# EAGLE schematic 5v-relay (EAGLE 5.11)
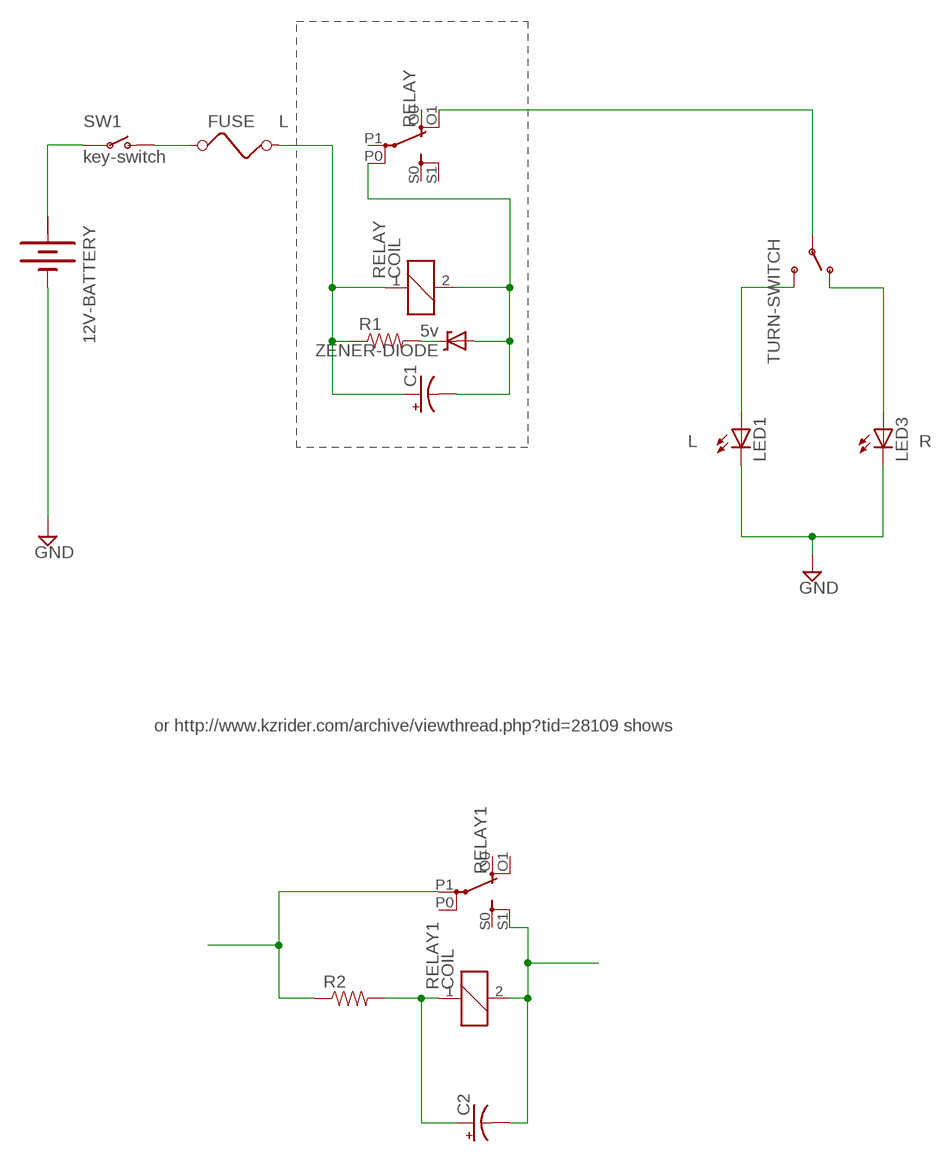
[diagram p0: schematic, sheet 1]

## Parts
12V-BATTERY  BATTERY  [BATTERY]
C1  CPOL-USA  [PANASONIC_A]
C2  CPOL-USA  [PANASONIC_A]
FUSE  FUSE  [FUSE]
LED1  LEDSQR2X5  [LED2X5]
LED3  LEDSQR2X5  [LED2X5]
R1  RESISTOR0402  [C0402]
R2  RESISTOR0402  [C0402]
RELAY  COIL  G2RE  [G2RE]
RELAY1  COIL  G2RE  [G2RE]
SW1  key-switch  SWITCH-SPST-2RA  [R_SW_TH]
TURN-SWITCH  SWITCH-SPSTPTH  [SWITCH-SPDT]
ZENER-DIODE  5v  DIODE-ZENERPTH  [DIODE-ZENER]

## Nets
GND: 12V-BATTERY.- LED1.K(C) LED3.K(C)
N$1: C1.+ FUSE.2 R1.1 RELAY.1
N$2: 12V-BATTERY.+ SW1.P$4(P)
N$3: C1.- RELAY.2 RELAY.P0(2:P) ZENER-DIODE.P$2(A)
N$4: LED3.A TURN-SWITCH.1(O)
N$5: LED1.A TURN-SWITCH.3(S)
N$6: RELAY.O1(2:O) TURN-SWITCH.2(P)
N$7: FUSE.1 SW1.P$3(O)
N$8: R1.2 ZENER-DIODE.P$1(C)
N$9: C2.- RELAY1.2 RELAY1.S1(2:S)
N$10: C2.+ R2.2 RELAY1.1
N$11: R2.1 RELAY1.P1(2:P)
Unconnected: RELAY1.O0(2:O) RELAY1.O1(2:O) RELAY1.P0(2:P) RELAY1.S0(2:S) RELAY.O0(2:O) RELAY.P1(2:P) RELAY.S0(2:S) RELAY.S1(2:S)

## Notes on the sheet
- L
- L | R
- or http://www.kzrider.com/archive/viewthread.php?tid=28109 shows

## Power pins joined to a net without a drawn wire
+: 12V-BATTERY.+@1(+)

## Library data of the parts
12V-BATTERY = special:BATTERY: BATTERY
C1 C2 = rcl:CPOL-US: POLARIZED CAPACITOR, American symbol
FUSE = special:FUSE: FUSE
LED1 LED3 = led:LED: LED
R1 R2 = SparkFun:RESISTOR: Resistor
RELAY RELAY1 = relay:G2RE: RELAY 1 x switch, high current, Omron; OC_FARNELL: unknown; OC_NEWARK: unknown
SW1 = SparkFun:SWITCH-SPST-2
TURN-SWITCH = SparkFun:SWITCH-SPST: SPST Switch Simple slide switch. Spark Fun Electronics SKU : COM-00102
ZENER-DIODE = SparkFun2011-02-20:DIODE-ZENER: Zener Diode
